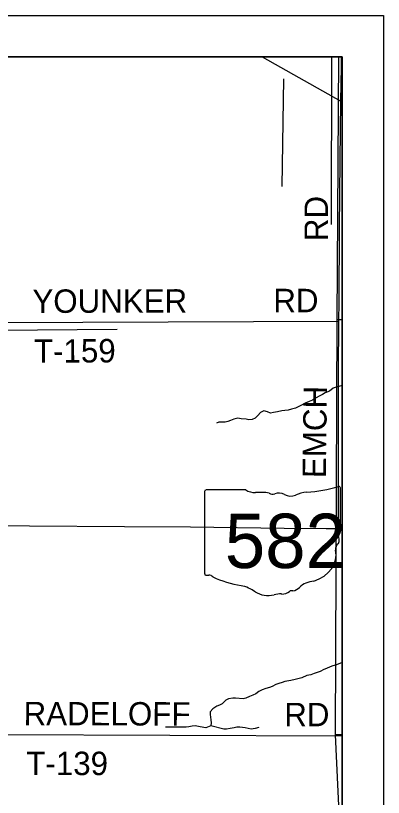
# Model space of a CAD drawing. Extents: x -8.3 to 42.1, y 0 to 22.
# Drawn here: x 8.107 to 9, y 19.103 to 21 of the extents above; entities that cross this region are included whole.
import ezdxf

# ---------------------------------------------------------------- set-up
doc = ezdxf.new("R2010")
doc.units = 0
for name, color, linetype in [('Default', 7, 'Continuous'), ('GM_X_Minor_River', 7, 'Continuous'), ('GM_X_State_Location', 7, 'Continuous'), ('GM_X_State_Route', 7, 'Continuous'), ('GM_X_State_Shield', 7, 'Continuous'), ('GM_X_Township_Road', 7, 'Continuous'), ('GM_X_Township_Road_Text', 7, 'Continuous'), ('GM_X_US_Route', 7, 'Continuous'), ('SH_Cut_Line', 7, 'Continuous'), ('SH_Data', 7, 'Continuous')]:
    doc.layers.add(name, color=color, linetype=linetype)

msp = doc.modelspace()

# ---------------------------------------------------------------- linework, layer by layer
at = {"layer": 'Default'}
for points in [[(8.9, 20.2623), (8.9, 20.9), (8.8911, 20.9), (8.8871, 20.2619)], [(8.9, 19.2548), (8.9, 20.2623), (8.8871, 20.2619), (8.8831, 19.2542)], [(8.9, 18.8937), (8.9, 19.2548), (8.8831, 19.2542)]]:
    msp.add_lwpolyline(points, close=True, dxfattribs=at)
at = {"layer": 'GM_X_Minor_River'}
for p, q in [((8.8743, 20.9), (8.8731, 20.4934)), ((8.7573, 20.8466), (8.7537, 20.5852)), ((8.3532, 20.238), (7.9567, 20.2345))]:
    msp.add_line(p, q, dxfattribs=at)
for points in [[(8.9, 20.102), (8.8918, 20.0998), (8.885, 20.0979), (8.8778, 20.0959), (8.8695, 20.0887), (8.8585, 20.0844), (8.8521, 20.0806), (8.8441, 20.076), (8.8369, 20.0726), (8.8275, 20.0664), (8.8195, 20.0637), (8.8104, 20.0591), (8.8013, 20.0542), (8.7949, 20.0515), (8.7862, 20.0472), (8.7767, 20.0449), (8.7684, 20.0422), (8.7604, 20.0414), (8.7532, 20.0406), (8.7429, 20.0383), (8.7335, 20.0371), (8.7255, 20.0352), (8.7187, 20.0385), (8.7099, 20.0404), (8.7016, 20.0369), (8.6952, 20.0297), (8.6884, 20.0232), (8.6812, 20.0197), (8.6736, 20.0193), (8.6664, 20.0208), (8.6542, 20.0215)], [(8.6542, 20.0215), (8.6462, 20.0226), (8.6364, 20.0206), (8.6284, 20.0176), (8.622, 20.0152), (8.6155, 20.0133), (8.6087, 20.0133), (8.6007, 20.0129), (8.5943, 20.0105)], [(8.9, 19.4295), (8.8959, 19.4283), (8.8861, 19.4245), (8.8773, 19.4218), (8.8705, 19.4195), (8.8618, 19.4156), (8.8554, 19.4129), (8.8467, 19.4083), (8.8395, 19.4056), (8.8319, 19.4033), (8.8235, 19.4002), (8.8144, 19.3983), (8.8023, 19.3929), (8.7921, 19.3906), (8.7856, 19.389), (8.775, 19.3863), (8.7606, 19.3836), (8.7542, 19.3813), (8.7458, 19.3793), (8.739, 19.3766), (8.7295, 19.3716), (8.7231, 19.3693), (8.7148, 19.367)], [(8.7148, 19.367), (8.7053, 19.3632), (8.6977, 19.3593), (8.6901, 19.354), (8.6826, 19.3509), (8.6746, 19.3474), (8.6663, 19.3436), (8.6591, 19.342), (8.6409, 19.3435), (8.6344, 19.3431), (8.6238, 19.3415), (8.617, 19.3384), (8.6087, 19.3296), (8.6018, 19.3262), (8.5954, 19.3239), (8.5859, 19.3177), (8.5791, 19.3105), (8.5792, 19.304), (8.5803, 19.2972), (8.5811, 19.2908), (8.5815, 19.2836), (8.5812, 19.2763)], [(8.5813, 19.2763), (8.569, 19.2717), (8.5546, 19.2739), (8.5425, 19.2758), (8.5352, 19.2753), (8.5273, 19.2738), (8.5208, 19.273), (8.5114, 19.2726), (8.5034, 19.2733), (8.495, 19.2732), (8.4882, 19.2728), (8.4711, 19.2727)], [(8.6977, 19.272), (8.6886, 19.2693), (8.6791, 19.2681), (8.6719, 19.27), (8.6647, 19.2711), (8.651, 19.2733), (8.6442, 19.2733), (8.6377, 19.271), (8.6275, 19.2698), (8.6191, 19.2682), (8.6123, 19.2678), (8.5812, 19.2763)]]:
    msp.add_lwpolyline(points, dxfattribs=at)
at = {"layer": 'GM_X_State_Route'}
msp.add_lwpolyline([(7.9393, 19.763), (8.1406, 19.7613), (8.3709, 19.76), (8.5318, 19.7588), (8.7592, 19.7563), (8.8612, 19.7549), (8.8908, 19.7552), (8.9, 19.7557)], dxfattribs=at)
at = {"layer": 'GM_X_State_Shield'}
for p, q in [((8.6657, 19.8486), (8.5692, 19.8486)), ((8.8955, 19.7489), (8.8955, 19.8536)), ((8.5659, 19.8452), (8.5659, 19.645)), ((8.8955, 19.7489), (8.8955, 19.7489))]:
    msp.add_line(p, q, dxfattribs=at)
for centre, major_axis, start_param, end_param in [((8.5697, 19.8456), (0.00382, 0), 1.712693, 3.28349), ((8.6887, 19.8718), (0.037, 0), 4.042523, 4.731795), ((8.7781, 20.1214), (0.3495, 0), 4.814394, 5.042369), ((8.8919, 19.854), (0.00367, 0), 6.141152, 7.989035), ((8.701, 19.7363), (0.133, 0), 1.404758, 1.657858), ((8.7312, 19.8466), (0.0107, 0), 3.836095, 5.185415), ((8.7468, 19.8235), (0.0222, 0), 0.950623, 2.079405), ((8.7755, 19.8552), (0.0267, 0), 4.081561, 5.145723), ((8.8227, 19.7875), (0.0703, 0), 1.699011, 2.107814), ((8.8947, 19.7412), (0.00568, 0), 1.883978, 3.671073), ((8.8586, 19.728), (0.0341, 0), 5.934695, 6.695948), ((8.8916, 19.7485), (0.00393, 0), 5.05454, 6.418171), ((8.9087, 19.7051), (0.0248, 0), 2.387724, 3.262537), ((8.7977, 19.6918), (0.0874, 0), 5.101752, 6.440018), ((8.5698, 19.6446), (0.00385, 0), 3.00124, 4.508301), ((8.5703, 19.6651), (0.0294, 0), 4.665946, 4.897461), ((8.5763, 19.6335), (0.0106, 0), 0.519207, 1.627899), ((8.7102, 19.8133), (0.2524, 0), 4.195997, 4.488961), ((8.8346, 19.5889), (0.0479, 0), 1.647645, 2.488434), ((8.6349, 19.5551), (0.079, 0), 0.823519, 1.323587), ((8.7203, 19.6325), (0.0501, 0), 4.026481, 4.996735), ((8.753, 19.6175), (0.0267, 0), 4.691044, 5.507374), ((8.7771, 19.5981), (0.00752, 0), 1.147584, 2.315152), ((8.7739, 19.6256), (0.0282, 0), 4.937069, 5.64225), ((8.7493, 19.5633), (0.0412, 0), 1.495662, 1.94098)]:
    msp.add_ellipse(centre, major_axis=major_axis, ratio=0.8, start_param=start_param, end_param=end_param, dxfattribs=at)
at = {"layer": 'GM_X_Township_Road'}
for p, q in [((7.9473, 20.2551), (8.8918, 20.2586)), ((7.9303, 19.2556), (8.9, 19.2515))]:
    msp.add_line(p, q, dxfattribs=at)
for points in [[(8.9, 16.8007), (8.9, 20.9), (7.9572, 20.9)], [(8.8963, 20.7926), (8.8982, 20.876), (8.8984, 20.9)], [(8.8908, 19.7552), (8.8908, 19.9433), (8.8912, 20.1344), (8.8918, 20.2586), (8.8923, 20.3052), (8.8938, 20.4824), (8.8948, 20.6484), (8.8963, 20.7926)]]:
    msp.add_lwpolyline(points, dxfattribs=at)
at = {"layer": 'GM_X_US_Route'}
msp.add_lwpolyline([(8.7054, 20.9), (8.8963, 20.7926), (8.9, 20.7905)], dxfattribs=at)
at = {"layer": 'SH_Cut_Line'}
msp.add_lwpolyline([(8.9, 14.1), (8.9, 20.9), (7.9572, 20.9)], dxfattribs=at)
at = {"layer": 'SH_Data'}
for p, q in [((2, 21), (9, 21)), ((9, 21), (9, 14)), ((2.1, 20.9), (8.9, 20.9)), ((8.9, 20.9), (8.9, 14.1))]:
    msp.add_line(p, q, dxfattribs=at)

# ---------------------------------------------------------------- texts
at = {"layer": 'GM_X_State_Location'}
msp.add_text('582', height=0.000189, rotation=0, dxfattribs=at).set_placement((8.6602, 19.718))
for s in ['s', 'r']:
    msp.add_text(s, height=0.000189, dxfattribs=at).set_placement((8.727, 19.7318))
at = {"layer": 'GM_X_State_Shield'}
msp.add_text('582', height=0.13184, dxfattribs=at).set_placement((8.6149, 19.6592))
at = {"layer": 'GM_X_Township_Road_Text'}
for s, rotation, p in [('RD', 90, (8.8653, 20.4527)), ('YOUNKER', 0.1412, (8.1476, 20.2784)), ('RD', 0, (8.7327, 20.2801)), ('T-159', 0.2818, (8.1515, 20.1574)), ('EMCH', 89.2867, (8.8603, 19.8772)), ('RADELOFF', 359.8666, (8.1261, 19.2776)), ('RD', 0, (8.7593, 19.2751)), ('T-139', 0, (8.1327, 19.1566))]:
    msp.add_text(s, height=0.05682, rotation=rotation, dxfattribs=at).set_placement(p)

doc.saveas('drawing.dxf')
